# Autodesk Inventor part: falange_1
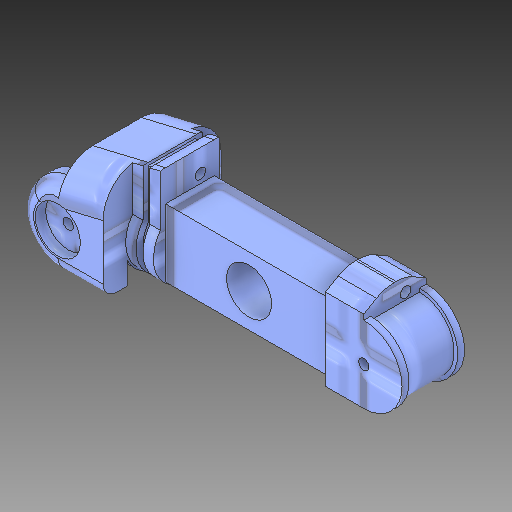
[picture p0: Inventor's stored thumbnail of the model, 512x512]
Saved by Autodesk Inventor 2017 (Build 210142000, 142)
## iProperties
Created: 2017-05
Part Number: falange_1
Material: Generic
Document SubType Name: Modeling
Designer: alez_
Density: 1 g/cm^3
Appearance: Default
Author: alez_
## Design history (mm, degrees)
derived "Falange_1.ipt" dims "d0" = 11
feature "Solid1::Falange_1.ipt" dims "d0" = 11
tag "TaggingFeature1"
body "Solid1"
